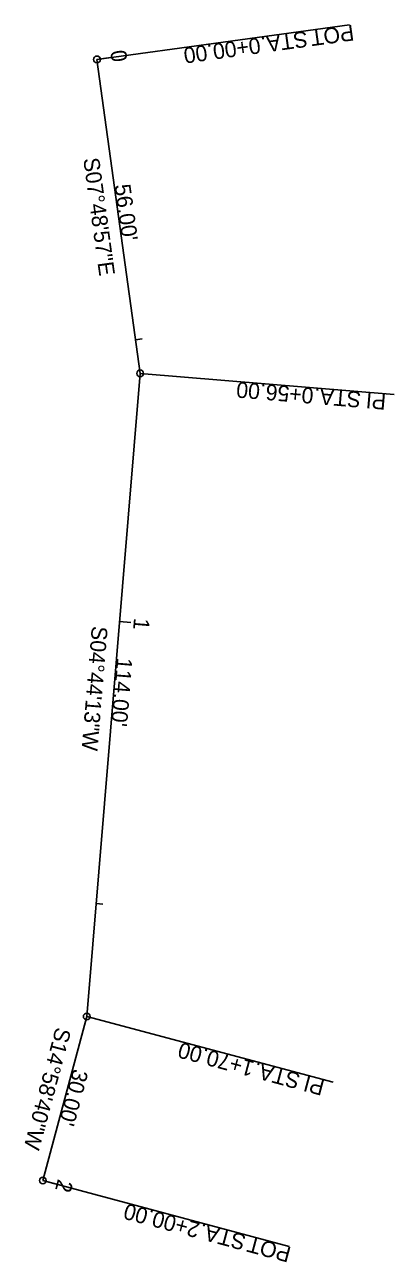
# Model space of a CAD drawing. Extents: x 151324 to 151389, y 410497 to 410715.
import ezdxf

# ---------------------------------------------------------------- set-up
doc = ezdxf.new("R2010")
doc.units = 0
for name, color, linetype in [('RW_X_CL', 7, 'Continuous'), ('RW_X_CL_100_Bearings', 7, 'Continuous'), ('RW_X_CL_100_Cardinal_Points', 7, 'Continuous'), ('RW_X_CL_100_Curve_Data', 7, 'Continuous'), ('RW_X_CL_100_Stations', 7, 'Continuous')]:
    doc.layers.add(name, color=color, linetype=linetype)

msp = doc.modelspace()

# ---------------------------------------------------------------- linework, layer by layer
at = {"layer": 'RW_X_CL'}
for p, q in [((151336.62, 410709.31), (151344.24, 410653.84)), ((151344.24, 410653.84), (151334.82, 410540.22)), ((151334.82, 410540.22), (151327.07, 410511.24))]:
    msp.add_line(p, q, dxfattribs=at)
at = {"layer": 'RW_X_CL_100_Cardinal_Points'}
for p, q in [((151336.62, 410709.31), (151381.2, 410715.43)), ((151344.24, 410653.84), (151389.08, 410650.12)), ((151334.82, 410540.22), (151378.29, 410528.59)), ((151327.07, 410511.24), (151370.54, 410499.61))]:
    msp.add_line(p, q, dxfattribs=at)
for centre in [(151336.62, 410709.31), (151344.24, 410653.84), (151334.82, 410540.22), (151327.07, 410511.24)]:
    msp.add_circle(centre, 0.6, dxfattribs=at)
at = {"layer": 'RW_X_CL_100_Stations'}
for p, q in [((151336.62, 410709.31), (151338.6, 410709.59)), ((151343.42, 410659.78), (151344.61, 410659.94)), ((151340.6, 410609.99), (151342.6, 410609.82)), ((151336.47, 410560.16), (151337.67, 410560.06)), ((151327.07, 410511.24), (151329, 410510.73))]:
    msp.add_line(p, q, dxfattribs=at)

# ---------------------------------------------------------------- texts
at = {"layer": 'RW_X_CL_100_Bearings'}
for s, rotation, p in [('S07°48\'57"E', 277.8157, (151334.19, 410691.76)), ('S04°44\'13"W', 265.2631, (151335.73, 410609.28)), ('S14°58\'40"W', 255.0221, (151329.38, 410538.46))]:
    msp.add_text(s, height=2.8, rotation=rotation, dxfattribs=at).set_placement(p)
at = {"layer": 'RW_X_CL_100_Cardinal_Points'}
for s, rotation, p in [('POT', 187.8157, (151381.77, 410715.47)), ('0+00.00', 187.8157, (151365.27, 410713.2)), (' STA. ', 187.8157, (151374.63, 410714.49)), ('0+56.00', 175.2631, (151374.94, 410651.25)), (' STA. ', 175.2631, (151384.36, 410650.47)), ('PI', 175.2631, (151387.74, 410650.19)), ('1+70.00', 165.0221, (151364.58, 410532.22)), (' STA. ', 165.0221, (151373.71, 410529.78)), ('PI', 165.0221, (151376.99, 410528.9)), ('2+00.00', 165.0221, (151354.99, 410503.73)), (' STA. ', 165.0221, (151364.12, 410501.29)), ('POT', 165.0221, (151371.07, 410499.43))]:
    msp.add_text(s, height=2.8, rotation=rotation, dxfattribs=at).set_placement(p)
at = {"layer": 'RW_X_CL_100_Curve_Data'}
for s, rotation, p in [("56.00'", 277.8157, (151339.71, 410687.09)), ("114.00'", 265.2631, (151340.12, 410603.68)), ("30.00'", 255.0221, (151332.42, 410531.1))]:
    msp.add_text(s, height=2.8, rotation=rotation, dxfattribs=at).set_placement(p)
at = {"layer": 'RW_X_CL_100_Stations'}
for s, rotation, p in [('0', 277.8157, (151338.95, 410710.76)), ('1', 265.2631, (151343.17, 410610.69)), ('2', 255.0221, (151329.75, 410511.61))]:
    msp.add_text(s, height=2.8, rotation=rotation, dxfattribs=at).set_placement(p)

doc.saveas('drawing.dxf')
